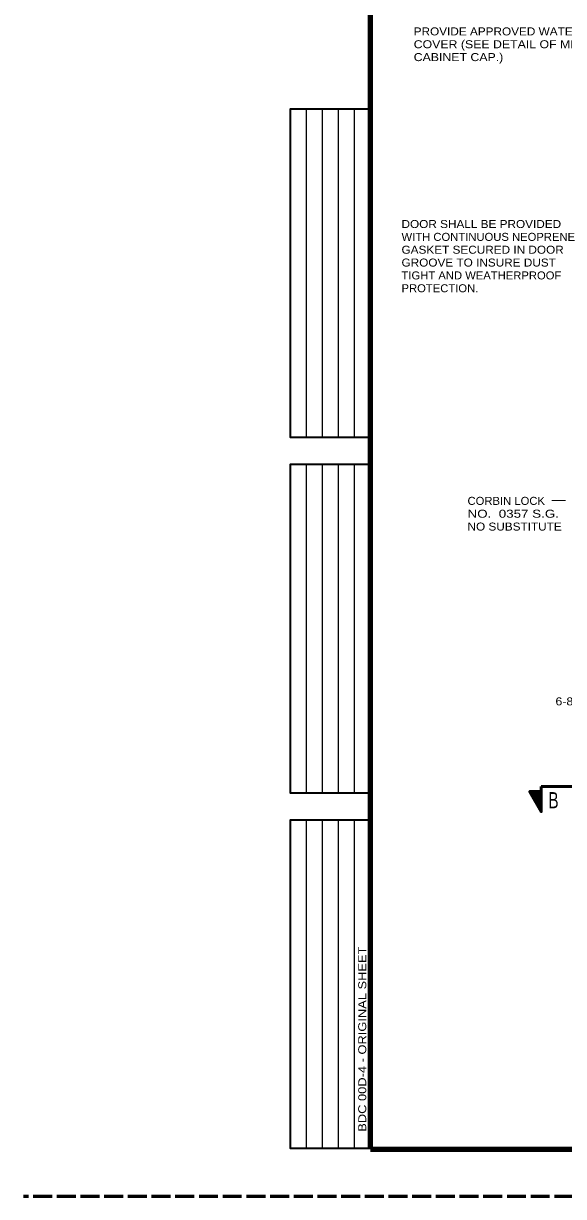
# Model space of a CAD drawing. Extents: x 312583 to 312853, y 144419 to 144586.
# Drawn here: x 312583.5 to 312634.8, y 144418.6 to 144530 of the extents above; entities that cross this region are included whole.
import ezdxf
from ezdxf.enums import TextEntityAlignment as Align

# ---------------------------------------------------------------- set-up
doc = ezdxf.new("R2010")
doc.units = 0
doc.header["$LTSCALE"] = 0.3
doc.linetypes.add('LONG_DASHED', pattern=[7.5, 6, -1.5])
doc.layers.add('1', color=7, linetype='Continuous', lineweight=13)

msp = doc.modelspace()

# ---------------------------------------------------------------- linework, layer by layer
at = {"layer": '1', "lineweight": 25}
for p, q in [((312610.4087, 144490.6573), (312610.4087, 144521.8756)), ((312611.9315, 144490.6573), (312611.9315, 144521.8756)), ((312613.4543, 144490.6573), (312613.4543, 144521.8756)), ((312614.9772, 144490.6573), (312614.9772, 144521.8756)), ((312610.4087, 144456.901), (312610.4087, 144488.1192)), ((312611.9315, 144456.901), (312611.9315, 144488.1192)), ((312613.4543, 144456.901), (312613.4543, 144488.1192)), ((312614.9772, 144456.901), (312614.9772, 144488.1192)), ((312610.4087, 144423.1446), (312610.4087, 144454.3629)), ((312611.9315, 144423.1446), (312611.9315, 144454.3629)), ((312613.4543, 144423.1446), (312613.4543, 144454.3629)), ((312614.9772, 144423.1446), (312614.9772, 144454.3629))]:
    msp.add_line(p, q, dxfattribs=at)
at = {"layer": '1'}
msp.add_line((312635.0199, 144484.6814), (312633.7017, 144484.6814), dxfattribs=at)
at = {"layer": '1', "lineweight": 53}
for p in [(312649.2953, 144457.5108), (312632.7046, 144457.0354)]:
    msp.add_line(p, (312632.7046, 144457.5108), dxfattribs=at)
at = {"layer": '1', "lineweight": 35}
for p, q in [((312631.6236, 144457.0354), (312631.6083, 144457.0201)), ((312631.6696, 144457.0354), (312631.6159, 144456.9971)), ((312631.7233, 144457.0354), (312631.6313, 144456.9818)), ((312631.7693, 144457.0354), (312631.6466, 144456.9588)), ((312631.8229, 144457.0354), (312631.6543, 144456.9358)), ((312631.8613, 144457.0354), (312631.6696, 144456.9204)), ((312631.9149, 144457.0354), (312631.6773, 144456.8974)), ((312631.9609, 144457.0354), (312631.6926, 144456.8744)), ((312632.0069, 144457.0354), (312631.7003, 144456.8591)), ((312632.0529, 144457.0354), (312631.7156, 144456.8284)), ((312632.1066, 144457.0354), (312631.7233, 144456.8131)), ((312632.1526, 144457.0354), (312631.7386, 144456.7901)), ((312632.1986, 144457.0354), (312631.7463, 144456.7671)), ((312632.2523, 144457.0354), (312631.7616, 144456.7518)), ((312632.2983, 144457.0354), (312631.7693, 144456.7288)), ((312632.3443, 144457.0354), (312631.7846, 144456.7134)), ((312632.3979, 144457.0354), (312631.7999, 144456.6904)), ((312632.4439, 144457.0354), (312631.8076, 144456.6674)), ((312632.4899, 144457.0354), (312631.8229, 144456.6521)), ((312632.5359, 144457.0354), (312631.8383, 144456.6291)), ((312632.5896, 144457.0354), (312631.8459, 144456.6061)), ((312632.6279, 144457.0354), (312631.8613, 144456.5908)), ((312632.6816, 144457.0354), (312631.8689, 144456.5601)), ((312632.7046, 144457.0201), (312631.8843, 144456.5448)), ((312632.7046, 144456.9894), (312631.8919, 144456.5218)), ((312632.7046, 144456.9588), (312631.9073, 144456.4988)), ((312632.7046, 144456.9358), (312631.9149, 144456.4834)), ((312632.7046, 144456.9051), (312631.9303, 144456.4604)), ((312632.6969, 144456.8821), (312631.9379, 144456.4374)), ((312632.6969, 144456.8514), (312631.9533, 144456.4221)), ((312632.7046, 144456.8284), (312631.9609, 144456.3991)), ((312632.7046, 144456.7978), (312631.9763, 144456.3761)), ((312632.7046, 144456.7671), (312631.9916, 144456.3608)), ((312632.7046, 144456.7441), (312631.9993, 144456.3378)), ((312632.7046, 144456.7134), (312632.0146, 144456.3148)), ((312632.7046, 144456.6828), (312632.0299, 144456.2918)), ((312632.7046, 144456.6598), (312632.0376, 144456.2764)), ((312632.6969, 144456.6291), (312632.0529, 144456.2534)), ((312632.7046, 144456.5984), (312632.0606, 144456.2304)), ((312632.7046, 144456.5754), (312632.0759, 144456.2151)), ((312632.7046, 144456.5524), (312632.0836, 144456.1921)), ((312632.7046, 144456.5218), (312632.0989, 144456.1691)), ((312632.7046, 144456.4911), (312632.1066, 144456.1538)), ((312632.7046, 144456.4604), (312632.1219, 144456.1308)), ((312632.7046, 144456.4374), (312632.1296, 144456.1078)), ((312632.7046, 144456.4068), (312632.1449, 144456.0924)), ((312632.6969, 144456.3838), (312632.1526, 144456.0618)), ((312632.7046, 144456.3531), (312632.1679, 144456.0464)), ((312632.7046, 144456.3301), (312632.1833, 144456.0234)), ((312632.7046, 144456.2994), (312632.1909, 144456.0004)), ((312632.7046, 144456.2688), (312632.2063, 144455.9851)), ((312632.7046, 144456.2458), (312632.2139, 144455.9621)), ((312632.7046, 144456.2151), (312632.2293, 144455.9391)), ((312632.7046, 144456.1844), (312632.2369, 144455.9238)), ((312632.7046, 144456.1614), (312632.2523, 144455.9008)), ((312632.7046, 144456.1308), (312632.2599, 144455.8778)), ((312632.7046, 144456.1001), (312632.2753, 144455.8624)), ((312632.7046, 144456.0771), (312632.2829, 144455.8394)), ((312632.7046, 144456.0541), (312632.2983, 144455.8164)), ((312632.7046, 144456.0234), (312632.3059, 144455.7934)), ((312632.7046, 144455.9928), (312632.3213, 144455.7781)), ((312632.7046, 144455.9621), (312632.3366, 144455.7551)), ((312632.7046, 144455.9391), (312632.3443, 144455.7321)), ((312632.7046, 144455.9084), (312632.3596, 144455.7168)), ((312632.7046, 144455.8854), (312632.3749, 144455.6938)), ((312632.7046, 144455.8548), (312632.3826, 144455.6708)), ((312632.7046, 144455.8318), (312632.3979, 144455.6554)), ((312632.7046, 144455.8011), (312632.4056, 144455.6324)), ((312632.7046, 144455.7704), (312632.4209, 144455.6094)), ((312632.7046, 144455.7474), (312632.4286, 144455.5941)), ((312632.7046, 144455.7168), (312632.4439, 144455.5634)), ((312632.7046, 144455.6938), (312632.4516, 144455.5481)), ((312632.7046, 144455.6631), (312632.4669, 144455.5251)), ((312632.7046, 144455.6324), (312632.4746, 144455.5021)), ((312632.7046, 144455.6094), (312632.4899, 144455.4868)), ((312632.7046, 144455.5788), (312632.4976, 144455.4638)), ((312632.7046, 144455.5558), (312632.5129, 144455.4408)), ((312632.7046, 144455.5251), (312632.5283, 144455.4254)), ((312632.7046, 144455.4944), (312632.5359, 144455.4024)), ((312632.7046, 144455.4638), (312632.5513, 144455.3794)), ((312632.7046, 144455.4408), (312632.5666, 144455.3641)), ((312632.7046, 144455.4101), (312632.5743, 144455.3411)), ((312632.7046, 144455.3871), (312632.5896, 144455.3181)), ((312632.7046, 144455.3641), (312632.5973, 144455.2951)), ((312632.7046, 144455.3334), (312632.6126, 144455.2798)), ((312632.7046, 144455.3028), (312632.6203, 144455.2568)), ((312632.7046, 144455.2721), (312632.6356, 144455.2338)), ((312632.7046, 144455.2491), (312632.6433, 144455.2184)), ((312632.7046, 144455.2184), (312632.6586, 144455.1954)), ((312632.7046, 144455.1954), (312632.6663, 144455.1724)), ((312632.7046, 144455.1648), (312632.6816, 144455.1571)), ((312632.7046, 144455.1341), (312632.6893, 144455.1341))]:
    msp.add_line(p, q, dxfattribs=at)
at = {"layer": '1', "lineweight": 158}
msp.add_line((312616.5, 144423.0846), (312849, 144423.0846), dxfattribs=at)
at = {"layer": '1', "linetype": 'LONG_DASHED', "lineweight": 60}
msp.add_line((312851.75, 144418.5846), (312583.526, 144418.5846), dxfattribs=at)
msp.add_line((312851.75, 144418.5846), (312583.526, 144418.5846), dxfattribs=at)
at = {"layer": '1', "lineweight": 158}
msp.add_lwpolyline([(312616.5, 144423.1446), (312616.5, 144585.0846), (312849, 144585.0846)], dxfattribs=at)
at = {"layer": '1', "lineweight": 35}
for points in [[(312616.5, 144490.6573), (312608.8858, 144490.6573), (312608.8858, 144521.8756), (312616.5, 144521.8756)], [(312616.5, 144456.901), (312608.8858, 144456.901), (312608.8858, 144488.1192), (312616.5, 144488.1192)], [(312616.5, 144423.1446), (312608.8858, 144423.1446), (312608.8858, 144454.3629), (312616.5, 144454.3629)]]:
    msp.add_lwpolyline(points, dxfattribs=at)
at = {"layer": '1', "lineweight": 53}
msp.add_lwpolyline([(312632.7046, 144457.0354), (312631.5929, 144457.0354), (312632.7046, 144455.1188)], close=True, dxfattribs=at)

# ---------------------------------------------------------------- texts
at = {"layer": '1'}
for s, width, p in [('PROVIDE APPROVED WATERTIGHT', 1.1, (312620.5885, 144528.8469)), ('COVER (SEE DETAIL OF METER', 1.15, (312620.5885, 144527.6269)), ('CABINET CAP.)', 1.15, (312620.5885, 144526.4069)), ('DOOR SHALL BE PROVIDED', 1.1, (312619.4332, 144510.5554)), ('WITH CONTINUOUS NEOPRENE', 1.05, (312619.4332, 144509.3354)), ('GASKET SECURED IN DOOR', 1.1, (312619.4332, 144508.1154)), ('GROOVE TO INSURE DUST', 1.1, (312619.4332, 144506.8954)), ('TIGHT AND WEATHERPROOF', 1.05, (312619.4332, 144505.6754)), ('PROTECTION.', 1.05, (312619.4332, 144504.4554)), ('CORBIN LOCK', 1.05, (312625.7009, 144484.2653)), ('NO.  0357 S.G.', 1.25, (312625.7009, 144483.0453)), ('NO SUBSTITUTE', 1.1, (312625.7009, 144481.8253)), ('6-8', 1.15, (312634.0518, 144465.225))]:
    msp.add_text(s, height=0.76, dxfattribs=dict(at, width=width)).set_placement(p)
at = {"layer": '1', "width": 0.7}
msp.add_text('B', height=1.533, dxfattribs=at).set_placement((312633.8661, 144455.4561), align=Align.CENTER)
at = {"layer": '1', "width": 1.2}
msp.add_text('BDC 00D-4 - ORIGINAL SHEET', height=0.7614, rotation=90, dxfattribs=at).set_placement((312616.0832, 144424.7374))

doc.saveas('drawing.dxf')
